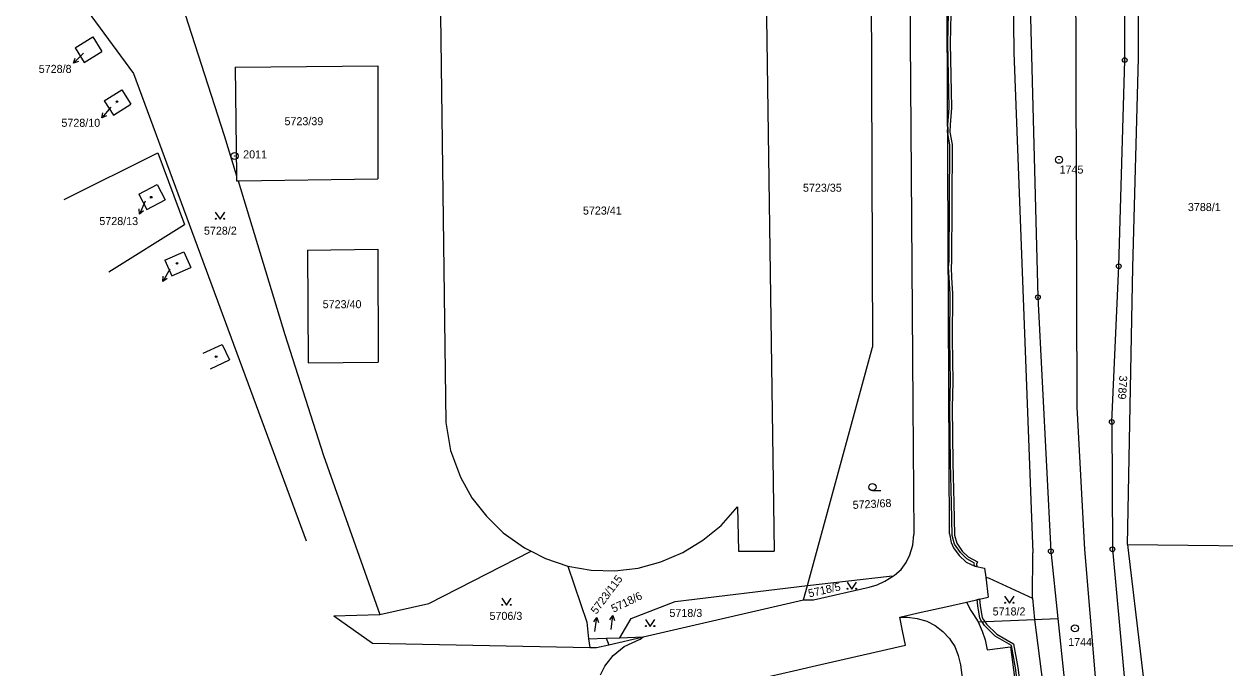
# Model space of a CAD drawing. Extents: x -735092 to -733385, y -1122435 to -1118992.
# Drawn here: x -734594.1 to -734339.7, y -1120993.3 to -1120856.8 of the extents above; entities that cross this region are included whole.
import ezdxf

# ---------------------------------------------------------------- set-up
doc = ezdxf.new("R2010")
doc.units = 0
for name, color, linetype in [('Vrstva 1', 7, 'Continuous'), ('Vrstva 10', 7, 'Continuous'), ('Vrstva 16', 7, 'Continuous'), ('Vrstva 17', 7, 'Continuous'), ('Vrstva 18', 7, 'Continuous'), ('Vrstva 19', 7, 'Continuous'), ('Vrstva 25', 7, 'Continuous'), ('Vrstva 27', 7, 'Continuous')]:
    doc.layers.add(name, color=color, linetype=linetype)

msp = doc.modelspace()

# ---------------------------------------------------------------- linework, layer by layer
at = {"layer": 'Vrstva 1'}
for points in [[(-734385.07, -1120787.44), (-734384.26, -1120862.83)], [(-734360.75, -1120864.43), (-734360.71, -1120809.25)], [(-734357.8, -1120864.02), (-734357.71, -1120809.04)], [(-734414.66, -1120810.81), (-734414.18, -1120925.28)], [(-734406.54, -1120815.41), (-734406.21, -1120860)], [(-734397.87, -1120964.88), (-734398.51, -1120823.51)], [(-734437.09, -1120825.9), (-734435.05, -1120968.54)], [(-734594.08, -1120835.72), (-734570.84, -1120867.3)], [(-734564.11, -1120841.78), (-734551.64, -1120880.4)], [(-734380.93, -1120847.29), (-734379.15, -1120914.72)], [(-734505.78, -1120854.81), (-734504.64, -1120941.29)], [(-734583.24, -1120861.86), (-734579.52, -1120859.52)], [(-734579.52, -1120859.52), (-734577.57, -1120862.61)], [(-734406.21, -1120860), (-734405.95, -1120898.21)], [(-734583.24, -1120861.86), (-734581.3, -1120864.96)], [(-734581.3, -1120864.96), (-734577.57, -1120862.61)], [(-734384.26, -1120862.83), (-734380.23, -1120968.9)], [(-734362, -1120908.13), (-734360.75, -1120864.43)], [(-734359.04, -1120908.37), (-734357.8, -1120864.02)], [(-734570.84, -1120867.3), (-734534.27, -1120966.34)], [(-734549.34, -1120865.95), (-734519.1, -1120865.63)], [(-734549.34, -1120865.95), (-734549.01, -1120888.95)], [(-734519.1, -1120865.63), (-734519.05, -1120889.63)], [(-734577.09, -1120873.04), (-734573.37, -1120870.71)], [(-734577.09, -1120873.04), (-734575.13, -1120876.13)], [(-734573.37, -1120870.71), (-734571.41, -1120873.78)], [(-734575.13, -1120876.13), (-734571.41, -1120873.78)], [(-734551.64, -1120880.4), (-734549.01, -1120888.95)], [(-734585.57, -1120894.02), (-734565.69, -1120884.12)], [(-734565.69, -1120884.12), (-734560.09, -1120899.3)], [(-734569.74, -1120892.83), (-734565.82, -1120890.82)], [(-734565.82, -1120890.82), (-734564.15, -1120894.06)], [(-734549.01, -1120888.95), (-734549, -1120890.02)], [(-734549, -1120890.02), (-734548.68, -1120890.02)], [(-734548.68, -1120890.02), (-734519.05, -1120889.63)], [(-734548.68, -1120890.02), (-734538.79, -1120922.62)], [(-734569.74, -1120892.83), (-734568.06, -1120896.08)], [(-734568.06, -1120896.08), (-734564.15, -1120894.06)], [(-734405.95, -1120898.21), (-734405.67, -1120937.42)], [(-734576.1, -1120909.29), (-734560.09, -1120899.3)], [(-734564.24, -1120906.83), (-734560.2, -1120905.08)], [(-734560.2, -1120905.08), (-734558.74, -1120908.41)], [(-734533.96, -1120904.72), (-734519.06, -1120904.52)], [(-734533.96, -1120904.72), (-734533.83, -1120928.59)], [(-734519.06, -1120904.52), (-734519.01, -1120928.45)], [(-734564.24, -1120906.83), (-734562.77, -1120910.18)], [(-734562.77, -1120910.18), (-734558.74, -1120908.41)], [(-734363.49, -1120941.14), (-734362, -1120908.13)], [(-734360.14, -1120967.09), (-734359.04, -1120908.37)], [(-734379.15, -1120914.72), (-734376.41, -1120968.55)], [(-734538.79, -1120922.62), (-734530.6, -1120948.24)], [(-734556.07, -1120926.58), (-734552.09, -1120924.71)], [(-734552.09, -1120924.71), (-734550.54, -1120928.01)], [(-734428, -1120975.81), (-734414.18, -1120925.28)], [(-734554.52, -1120929.89), (-734550.54, -1120928.01)], [(-734533.83, -1120928.59), (-734519.01, -1120928.45)], [(-734405.67, -1120937.42), (-734405.43, -1120965.02)], [(-734504.64, -1120941.29), (-734503.66, -1120947.21)], [(-734363.49, -1120941.14), (-734363.34, -1120968.14)], [(-734530.6, -1120948.24), (-734518.66, -1120981.97)], [(-734503.66, -1120947.21), (-734501.54, -1120952.83)], [(-734501.54, -1120952.83), (-734499.16, -1120957.23)], [(-734499.16, -1120957.23), (-734496.05, -1120961.1)], [(-734446.27, -1120963.07), (-734442.81, -1120959.11)], [(-734442.81, -1120959.11), (-734442.64, -1120968.52)], [(-734496.05, -1120961.1), (-734492.49, -1120964.64)], [(-734492.49, -1120964.64), (-734487.98, -1120967.82)], [(-734450.18, -1120966.17), (-734446.27, -1120963.07)], [(-734454.42, -1120968.84), (-734450.18, -1120966.17)], [(-734406.31, -1120969.34), (-734405.69, -1120967.28)], [(-734405.69, -1120967.28), (-734405.43, -1120965.02)], [(-734397.87, -1120964.88), (-734397.54, -1120966.71)], [(-734397.54, -1120966.71), (-734397.05, -1120967.83)], [(-734360.14, -1120967.09), (-734360.07, -1120967.78)], [(-734360.14, -1120967.09), (-734321.52, -1120967.56)], [(-734508.29, -1120979.62), (-734486.58, -1120968.54)], [(-734487.98, -1120967.82), (-734486.58, -1120968.54)], [(-734486.58, -1120968.54), (-734483.53, -1120970.1)], [(-734459.05, -1120970.76), (-734454.42, -1120968.84)], [(-734442.64, -1120968.52), (-734435.05, -1120968.54)], [(-734407.09, -1120970.96), (-734406.31, -1120969.34)], [(-734397.05, -1120967.83), (-734395.86, -1120969.47)], [(-734395.86, -1120969.47), (-734394.36, -1120970.86)], [(-734380.33, -1120978.51), (-734380.23, -1120968.9)], [(-734376.41, -1120968.55), (-734374.92, -1120982.78)], [(-734363.34, -1120968.14), (-734357.6, -1121030.54)], [(-734360.07, -1120967.78), (-734351.82, -1121037.28)], [(-734483.53, -1120970.1), (-734478.77, -1120971.69)], [(-734478.77, -1120971.69), (-734474.75, -1120983.57)], [(-734478.77, -1120971.69), (-734473.86, -1120972.59)], [(-734468.83, -1120972.7), (-734463.91, -1120972.11)], [(-734463.91, -1120972.11), (-734459.05, -1120970.76)], [(-734409.53, -1120973.61), (-734408.17, -1120972.39)], [(-734408.17, -1120972.39), (-734407.09, -1120970.96)], [(-734394.36, -1120970.86), (-734392.49, -1120971.72)], [(-734392.49, -1120971.72), (-734390.49, -1120972.11)], [(-734390.49, -1120972.11), (-734390.22, -1120974.08)], [(-734473.86, -1120972.59), (-734468.83, -1120972.7)], [(-734428, -1120975.81), (-734410.63, -1120973.86)], [(-734413.21, -1120975.69), (-734411.57, -1120974.89)], [(-734411.57, -1120974.89), (-734409.74, -1120973.74)], [(-734410.63, -1120973.86), (-734409.74, -1120973.74)], [(-734409.74, -1120973.74), (-734409.53, -1120973.61)], [(-734390.22, -1120974.08), (-734389.66, -1120978.25)], [(-734390.22, -1120974.08), (-734389.51, -1120974.24)], [(-734389.51, -1120974.24), (-734380.33, -1120978.51)], [(-734456.02, -1120979.2), (-734428, -1120975.81)], [(-734428.82, -1120978.83), (-734428, -1120975.81)], [(-734426.73, -1120978.86), (-734414.93, -1120976.17)], [(-734414.93, -1120976.17), (-734413.21, -1120975.69)], [(-734518.66, -1120981.97), (-734508.29, -1120979.62)], [(-734465.4, -1120982.84), (-734456.02, -1120979.2)], [(-734462.8, -1120986.68), (-734428.82, -1120978.83)], [(-734428.82, -1120978.83), (-734426.73, -1120978.86)], [(-734398.06, -1120980.16), (-734394.31, -1120979.31)], [(-734394.31, -1120979.31), (-734389.66, -1120978.25)], [(-734394.31, -1120979.31), (-734393.4, -1120981.11), (-734392.83, -1120981.95), (-734391.83, -1120983.53)], [(-734380.33, -1120978.51), (-734379.85, -1120983)], [(-734528.39, -1120982.27), (-734518.66, -1120981.97)], [(-734528.39, -1120982.27), (-734520.23, -1120988.01)], [(-734408.45, -1120982.52), (-734404.5, -1120981.62)], [(-734408.45, -1120982.52), (-734407.76, -1120982.49), (-734406.76, -1120982.49), (-734404.74, -1120982.79), (-734402.7, -1120983.34), (-734400.92, -1120984.3), (-734399.29, -1120985.53), (-734397.91, -1120987.04), (-734397.67, -1120987.41), (-734396.79, -1120988.77), (-734396.05, -1120990.64), (-734395.57, -1120992.62)], [(-734407.19, -1120988.47), (-734407.84, -1120985.39), (-734408.45, -1120982.52)], [(-734404.5, -1120981.62), (-734398.06, -1120980.16)], [(-734474.75, -1120983.57), (-734474.43, -1120987.15)], [(-734467.8, -1120986.9), (-734465.4, -1120982.84)], [(-734391.83, -1120983.53), (-734379.85, -1120983)], [(-734391.83, -1120983.53), (-734390.95, -1120985.47), (-734390.33, -1120987.34), (-734389.88, -1120989.46)], [(-734379.85, -1120983), (-734374.92, -1120982.78)], [(-734379.85, -1120983), (-734370.57, -1121055.81)], [(-734374.92, -1120982.78), (-734369.85, -1121031.3)], [(-734474.43, -1120987.15), (-734470.65, -1120987)], [(-734474.43, -1120987.15), (-734474.14, -1120988.95)], [(-734470.65, -1120987), (-734467.8, -1120986.9)], [(-734470.65, -1120987), (-734470.12, -1120988.37)], [(-734470.12, -1120988.37), (-734462.8, -1120986.68)], [(-734467.8, -1120986.9), (-734462.8, -1120986.68)], [(-734466.84, -1120988.73), (-734463.49, -1120987.21)], [(-734463.49, -1120987.21), (-734462.8, -1120986.68)], [(-734520.23, -1120988.01), (-734474.14, -1120988.95)], [(-734474.14, -1120988.95), (-734472.72, -1120988.97)], [(-734472.72, -1120988.97), (-734470.12, -1120988.37)], [(-734469.22, -1120990.62), (-734466.84, -1120988.73)], [(-734455.69, -1120999.53), (-734430.99, -1120993.88), (-734425.2, -1120992.53), (-734407.19, -1120988.47)], [(-734389.88, -1120989.46), (-734384.96, -1120988.81), (-734380.72, -1121021.42)], [(-734470.97, -1120992.94), (-734469.22, -1120990.62)], [(-734395.57, -1120992.62), (-734394.02, -1121004.67), (-734393.62, -1121007.64), (-734391.13, -1121026.63)], [(-734471.84, -1120994.73), (-734470.97, -1120992.94)]]:
    msp.add_lwpolyline(points, dxfattribs=at)
at = {"layer": 'Vrstva 10'}
for points in [[(-734370.81, -1120938), (-734371.18, -1120819.86)], [(-734369.17, -1120968.19), (-734370.81, -1120938)], [(-734365.77, -1121009.51), (-734369.17, -1120968.19)]]:
    msp.add_lwpolyline(points, dxfattribs=at)
at = {"layer": 'Vrstva 25'}
for points in [[(-734581.49, -1120862.97), (-734583.611, -1120865.091)], [(-734582.55, -1120864.737), (-734583.611, -1120865.091), (-734583.257, -1120864.03)], [(-734575.67, -1120874.38), (-734577.606, -1120876.671)], [(-734576.579, -1120876.23), (-734577.606, -1120876.671), (-734577.342, -1120875.584)], [(-734568.727, -1120896.378), (-734569.594, -1120897.084), (-734569.638, -1120895.967)], [(-734568.36, -1120894.35), (-734569.594, -1120897.084)], [(-734553.53, -1120896.66), (-734552.53, -1120898.16), (-734551.53, -1120896.66)], [(-734563.14, -1120908.78), (-734564.671, -1120911.359)], [(-734563.731, -1120910.754), (-734564.671, -1120911.359), (-734564.591, -1120910.244)], [(-734414.22, -1120955.7), (-734412.47, -1120955.7)], [(-734419.58, -1120975.11), (-734418.58, -1120976.61), (-734417.58, -1120975.11)], [(-734492.8, -1120978.51), (-734491.8, -1120980.01), (-734490.8, -1120978.51)], [(-734386.2, -1120978.06), (-734385.2, -1120979.56), (-734384.2, -1120978.06)], [(-734473.303, -1120983.541), (-734472.673, -1120982.618), (-734472.314, -1120983.677)], [(-734473.08, -1120985.59), (-734472.673, -1120982.618)], [(-734469.861, -1120983.083), (-734469.239, -1120982.155), (-734468.87, -1120983.21)], [(-734469.62, -1120985.13), (-734469.239, -1120982.155)], [(-734462.36, -1120983.01), (-734461.36, -1120984.51), (-734460.36, -1120983.01)]]:
    msp.add_lwpolyline(points, dxfattribs=at)
for centre, radius in [((-734360.75, -1120864.43), 0.5), ((-734360.75, -1120864.43), 0.032), ((-734574.36, -1120873.24), 0.175), ((-734549.44, -1120884.77), 0.75), ((-734549.44, -1120884.77), 0.032), ((-734374.67, -1120885.56), 0.75), ((-734374.67, -1120885.56), 0.032), ((-734567.11, -1120893.51), 0.175), ((-734553.43, -1120898.06), 0.1), ((-734551.63, -1120898.06), 0.1), ((-734561.65, -1120907.52), 0.175), ((-734362, -1120908.13), 0.5), ((-734362, -1120908.13), 0.032), ((-734379.15, -1120914.72), 0.5), ((-734379.15, -1120914.72), 0.032), ((-734553.36, -1120927.29), 0.175), ((-734363.49, -1120941.14), 0.5), ((-734363.49, -1120941.14), 0.032), ((-734414.22, -1120954.95), 0.75), ((-734376.41, -1120968.55), 0.5), ((-734376.41, -1120968.55), 0.032), ((-734363.34, -1120968.14), 0.5), ((-734363.34, -1120968.14), 0.032), ((-734419.48, -1120976.51), 0.1), ((-734417.68, -1120976.51), 0.1), ((-734492.7, -1120979.91), 0.1), ((-734490.9, -1120979.91), 0.1), ((-734386.1, -1120979.46), 0.1), ((-734384.3, -1120979.46), 0.1), ((-734462.26, -1120984.41), 0.1), ((-734460.46, -1120984.41), 0.1), ((-734371.31, -1120984.89), 0.75), ((-734371.31, -1120984.89), 0.032)]:
    msp.add_circle(centre, radius, dxfattribs=at)
at = {"layer": 'Vrstva 27'}
for points in [[(-734392.12, -1120971.79), (-734392.49, -1120971.72), (-734392.62, -1120971.66), (-734392.66, -1120971.23), (-734392.59, -1120971.05), (-734394.2, -1120970.13), (-734395.58, -1120968.84), (-734396.82, -1120967.02), (-734397.3, -1120965.18), (-734397.48, -1120958.3), (-734397.71, -1120949.8), (-734397.81, -1120938.06), (-734397.67, -1120932.67), (-734397.8, -1120923.57), (-734397.77, -1120914.02), (-734397.94, -1120910.54), (-734398.07, -1120908.36), (-734397.94, -1120907.03), (-734397.86, -1120894.74), (-734397.84, -1120882.4), (-734398.25, -1120880), (-734398.26, -1120878.67), (-734398.24, -1120878.13), (-734397.96, -1120874.55), (-734398.24, -1120860.87), (-734398.1, -1120854.65)], [(-734392.12, -1120971.79), (-734392.49, -1120971.72), (-734392.62, -1120971.66), (-734392.66, -1120971.23), (-734392.59, -1120971.05), (-734394.2, -1120970.13), (-734395.58, -1120968.84), (-734396.82, -1120967.02), (-734397.3, -1120965.18), (-734397.48, -1120958.3), (-734397.71, -1120949.8), (-734397.81, -1120938.06), (-734397.67, -1120932.67), (-734397.8, -1120923.57), (-734397.77, -1120914.02), (-734397.94, -1120910.54), (-734398.07, -1120908.36), (-734397.94, -1120907.03), (-734397.86, -1120894.74), (-734397.84, -1120882.4), (-734398.25, -1120880), (-734398.26, -1120878.67), (-734398.24, -1120878.13), (-734397.96, -1120874.55), (-734398.24, -1120860.87), (-734398.1, -1120854.65)], [(-734397.6, -1120854.65), (-734397.74, -1120860.87), (-734397.46, -1120874.57), (-734397.74, -1120878.15), (-734397.8, -1120879.7), (-734397.34, -1120882.36), (-734397.36, -1120894.74), (-734397.44, -1120907.05), (-734397.57, -1120908.37), (-734397.44, -1120910.52), (-734397.27, -1120914), (-734397.3, -1120923.57), (-734397.17, -1120932.67), (-734397.31, -1120938.06), (-734397.21, -1120949.8), (-734396.98, -1120958.28), (-734396.8, -1120965.11), (-734396.36, -1120966.81), (-734395.2, -1120968.52), (-734393.9, -1120969.73), (-734391.97, -1120970.83), (-734392.16, -1120971.31), (-734392.12, -1120971.79)], [(-734397.6, -1120854.65), (-734397.74, -1120860.87), (-734397.46, -1120874.57), (-734397.74, -1120878.15), (-734397.8, -1120879.7), (-734397.34, -1120882.36), (-734397.36, -1120894.74), (-734397.44, -1120907.05), (-734397.57, -1120908.37), (-734397.44, -1120910.52), (-734397.27, -1120914), (-734397.3, -1120923.57), (-734397.17, -1120932.67), (-734397.31, -1120938.06), (-734397.21, -1120949.8), (-734396.98, -1120958.28), (-734396.8, -1120965.11), (-734396.36, -1120966.81), (-734395.2, -1120968.52), (-734393.9, -1120969.73), (-734391.97, -1120970.83), (-734392.16, -1120971.31), (-734392.12, -1120971.79)], [(-734398.25, -1120880), (-734398.3, -1120879.74), (-734398.26, -1120878.67), (-734398.25, -1120880)], [(-734392, -1120978.78), (-734391.51, -1120978.67)], [(-734378.77, -1121032.43), (-734378.89, -1121031.27), (-734379.24, -1121029.8), (-734379.32, -1121029.46), (-734379.37, -1121029.05), (-734380.21, -1121022.43), (-734381.53, -1121011.72), (-734382.54, -1121003.94), (-734383.93, -1120993.3), (-734384.76, -1120988.5), (-734388.19, -1120986.52), (-734390.44, -1120984.3), (-734390.99, -1120983.49), (-734391.08, -1120983.36), (-734391.45, -1120982.74), (-734391.88, -1120980.15), (-734392, -1120978.78)], [(-734391.51, -1120978.67), (-734391.38, -1120980.09), (-734390.97, -1120982.56)], [(-734390.97, -1120982.56), (-734390.66, -1120983.1), (-734390.41, -1120983.47), (-734390.06, -1120983.98), (-734387.89, -1120986.12), (-734384.3, -1120988.18), (-734383.43, -1120993.22), (-734382.04, -1121003.88)]]:
    msp.add_lwpolyline(points, dxfattribs=at)

# ---------------------------------------------------------------- texts
at = {"layer": 'Vrstva 16'}
for s, p in [('5728/8', (-734590.957, -1120867.15)), ('5728/10', (-734586.147, -1120878.58)), ('5728/13', (-734578.107, -1120899.41))]:
    msp.add_text(s, height=1.7, dxfattribs=at).set_placement(p)
for s, rotation, p in [('5723/115', 53.30043, (-734472.74, -1120982.031)), ('5718/6', 25.80021, (-734469.107, -1120981.603))]:
    msp.add_text(s, height=1.7, rotation=rotation, dxfattribs=at).set_placement(p)
at = {"layer": 'Vrstva 17'}
for s, p in [('2011', (-734547.62, -1120885.27)), ('1745', (-734374.56, -1120888.49)), ('1744', (-734372.73, -1120988.64))]:
    msp.add_text(s, height=1.7, dxfattribs=at).set_placement(p)
at = {"layer": 'Vrstva 18'}
for s, height, p in [('5728/8', 0.1, (-734581.05, -1120862.53)), ('5723/39', 1.7, (-734538.86, -1120878.24)), ('5723/35', 1.7, (-734428.95, -1120892.34)), ('5723/41', 1.7, (-734475.59, -1120897.18)), ('3788/1', 1.7, (-734347.35, -1120896.44)), ('5728/2', 1.7, (-734555.93, -1120901.45)), ('5723/40', 1.7, (-734530.76, -1120917.03)), ('5706/3', 1.7, (-734495.4, -1120983.1)), ('5718/3', 1.7, (-734457.26, -1120982.48)), ('5718/2', 1.7, (-734388.74, -1120982.16)), ('5718/6', 0.1, (-734469.75, -1120987.53)), ('5723/115', 0.1, (-734473.24, -1120988.02))]:
    msp.add_text(s, height=height, dxfattribs=at).set_placement(p)
for s, rotation, p in [('3789', 266.70212, (-734361.882, -1120931.261)), ('5723/68', 3.00002, (-734418.371, -1120959.58)), ('5718/5', 12.7001, (-734427.629, -1120978.351))]:
    msp.add_text(s, height=1.7, rotation=rotation, dxfattribs=at).set_placement(p)
at = {"layer": 'Vrstva 19'}
for s, p in [('5728/10', (-734575.05, -1120873.68)), ('5728/13', (-734568.02, -1120893.84)), ('5728/15', (-734562.6, -1120908.01)), ('5728/17', (-734553.49, -1120928.25))]:
    msp.add_text(s, height=0.1, dxfattribs=at).set_placement(p)

doc.saveas('drawing.dxf')
